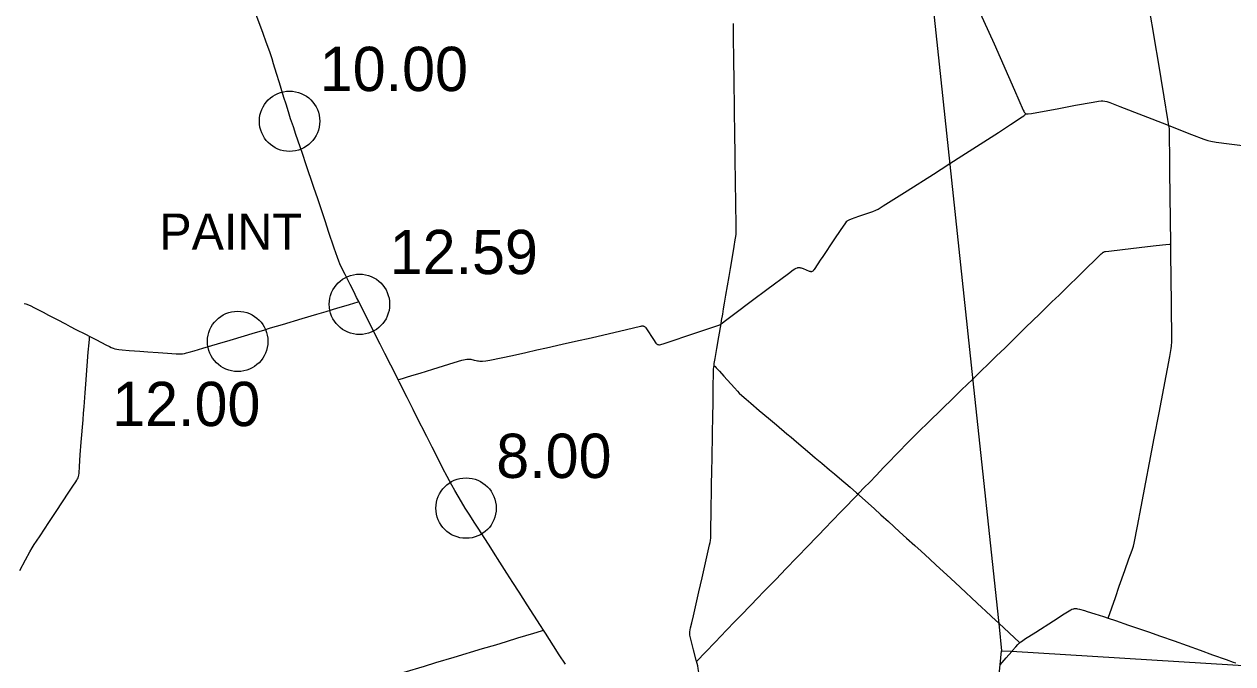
# Model space of a CAD drawing. Extents: x 1597222 to 1925846, y 496284 to 911751.
# Drawn here: x 1697422 to 1727439, y 592663 to 608558 of the extents above; entities that cross this region are included whole.
import ezdxf

# ---------------------------------------------------------------- set-up
doc = ezdxf.new("R2010")
doc.units = 0
for name, color, linetype in [('Default', 7, 'Continuous'), ('GM_X_County_Road', 7, 'Continuous'), ('GM_X_State_Route', 7, 'Continuous'), ('GM_X_Township', 7, 'Continuous'), ('GM_X_Township_Road', 7, 'Continuous'), ('GM_X_Township_Text', 7, 'Continuous')]:
    doc.layers.add(name, color=color, linetype=linetype)

msp = doc.modelspace()

# ---------------------------------------------------------------- linework, layer by layer
at = {"layer": 'Default'}
for centre in [(1704013, 606146), (1704013, 606146), (1705749, 601597), (1705749, 601597), (1702725, 600676), (1702725, 600676), (1708396, 596532), (1708396, 596532)]:
    msp.add_circle(centre, 750, dxfattribs=at)
at = {"layer": 'GM_X_County_Road'}
for points in [[(1719664, 612128), (1719709, 612028), (1720072, 611236), (1720382, 610549), (1720574, 610132), (1720984, 609237), (1721514, 608073), (1722019, 606916), (1722233, 606423), (1722246, 606395), (1722256, 606375), (1722265, 606360), (1722278, 606348), (1722291, 606338), (1722301, 606333)], [(1725853, 606038), (1725852, 606043), (1725828, 606188), (1725733, 606755), (1725581, 607661), (1725508, 608096), (1725457, 608403), (1725348, 609067)], [(1714729, 601108), (1714743, 601191), (1714771, 601353), (1714792, 601482), (1714817, 601628), (1714850, 601822), (1714930, 602291), (1714963, 602485), (1714987, 602631), (1715056, 603035), (1715083, 603197), (1715094, 603278), (1715101, 603343), (1715105, 603408), (1715107, 603490), (1715103, 603736), (1715100, 603916), (1715098, 604047), (1715095, 604244), (1715090, 604506), (1715087, 604720), (1715084, 604851), (1715081, 604998), (1715080, 605195), (1715079, 605326), (1715076, 605474), (1715074, 605687), (1715070, 605851), (1715069, 606031), (1715067, 606195), (1715063, 606425), (1715059, 606688), (1715056, 606934), (1715054, 607147), (1715046, 607672), (1715044, 607852), (1715040, 608049), (1715040, 608246), (1715036, 608574)], [(1722301, 606333), (1722308, 606331), (1722316, 606329), (1722325, 606327), (1722333, 606327), (1722341, 606327), (1722357, 606328), (1722439, 606341), (1723117, 606465), (1723536, 606543), (1723972, 606624), (1724101, 606645), (1724166, 606651), (1724214, 606650), (1724260, 606646), (1724310, 606633), (1724388, 606608), (1724632, 606513), (1725794, 606061), (1725853, 606038)], [(1720411, 605092), (1720708, 605283), (1720985, 605460), (1721619, 605869), (1721921, 606066), (1722209, 606255), (1722252, 606284), (1722277, 606303), (1722287, 606313), (1722293, 606322), (1722301, 606333)], [(1725853, 606038), (1726415, 605816), (1726722, 605698), (1726816, 605668), (1726896, 605650), (1727026, 605630), (1727351, 605587), (1727936, 605510), (1728701, 605408), (1729335, 605327), (1729562, 605296), (1729626, 605283), (1729673, 605269), (1729718, 605250), (1729760, 605226), (1729829, 605182), (1730604, 604603), (1730959, 604338), (1731603, 603858), (1731787, 603720), (1731905, 603631), (1732099, 603483), (1732167, 603429)], [(1725897, 603097), (1725877, 604895), (1725872, 605453), (1725867, 605469), (1725871, 605486), (1725870, 605535), (1725864, 605945), (1725863, 605969), (1725859, 606002), (1725853, 606038)], [(1714729, 601108), (1714738, 601114), (1714757, 601130), (1714803, 601167), (1715038, 601342), (1715511, 601696), (1715866, 601962), (1716404, 602366), (1716522, 602454), (1716564, 602481), (1716593, 602496), (1716624, 602506), (1716639, 602509), (1716656, 602510), (1716671, 602511), (1716687, 602509), (1716706, 602507), (1716721, 602503), (1716740, 602498), (1716768, 602488), (1716919, 602423), (1716939, 602418), (1716951, 602415), (1716960, 602414), (1716968, 602414), (1716975, 602414), (1716983, 602416), (1716990, 602418), (1716999, 602421), (1717013, 602428), (1717026, 602438), (1717037, 602450), (1717048, 602462), (1717142, 602603), (1717201, 602693), (1717263, 602786), (1717349, 602912), (1717459, 603076), (1717559, 603226), (1717694, 603432), (1717824, 603621), (1717856, 603659), (1717870, 603672), (1717881, 603680), (1717893, 603688), (1717909, 603697), (1717969, 603721), (1718155, 603786), (1718496, 603906), (1718573, 603935), (1718631, 603964), (1718758, 604041), (1719353, 604419), (1720005, 604831), (1720199, 604955), (1720411, 605092)], [(1720980, 599738), (1721574, 600315), (1721773, 600510), (1722020, 600751), (1722302, 601025), (1722466, 601186), (1722643, 601357), (1722948, 601655), (1723125, 601826), (1723383, 602078), (1723571, 602261), (1723817, 602503), (1724016, 602698), (1724167, 602849), (1724191, 602870), (1724204, 602880), (1724218, 602889), (1724233, 602896), (1724248, 602902), (1724264, 602907), (1724280, 602910), (1724361, 602921), (1724703, 602960), (1725111, 603007), (1725323, 603031), (1725534, 603056), (1725779, 603083), (1725877, 603095), (1725897, 603097)], [(1724345, 593802), (1724523, 594314), (1724620, 594593), (1724757, 594979), (1724860, 595274), (1724938, 595489), (1724969, 595583), (1724989, 595663), (1725070, 596082), (1725160, 596566), (1725487, 598274), (1725606, 598902), (1725723, 599515), (1725875, 600304), (1725909, 600498), (1725917, 600558), (1725920, 600596), (1725922, 600629), (1725923, 600679), (1725913, 601614), (1725900, 602861), (1725897, 603097)], [(1706709, 599724), (1706727, 599729), (1706814, 599756), (1706914, 599787), (1707052, 599829), (1707256, 599890), (1707570, 599987), (1708104, 600148), (1708292, 600207), (1708371, 600228), (1708419, 600236), (1708428, 600237), (1708440, 600238), (1708452, 600238), (1708468, 600237), (1708492, 600235), (1708517, 600231), (1708601, 600212), (1708646, 600200), (1708677, 600194), (1708703, 600189), (1708742, 600185), (1708808, 600184), (1708889, 600191), (1708986, 600207), (1709548, 600329), (1709884, 600403), (1710156, 600463), (1710396, 600519), (1710780, 600605), (1711116, 600682), (1711501, 600768), (1712380, 600971), (1712731, 601055), (1712747, 601058), (1712765, 601060), (1712780, 601061), (1712796, 601059), (1712805, 601057), (1712812, 601054), (1712826, 601046), (1712839, 601037), (1712849, 601026), (1712861, 601013), (1713067, 600696), (1713094, 600655), (1713110, 600634), (1713126, 600617), (1713139, 600608), (1713154, 600601), (1713169, 600596), (1713185, 600593), (1713202, 600593), (1713234, 600598), (1713313, 600622), (1714105, 600891), (1714650, 601074), (1714697, 601088), (1714706, 601093), (1714712, 601096), (1714721, 601102), (1714729, 601108)], [(1714554, 600072), (1714561, 600124), (1714582, 600254), (1714624, 600496), (1714675, 600787), (1714729, 601108)], [(1714122, 592728), (1714115, 592755), (1714049, 593009), (1713976, 593278), (1713960, 593342), (1713954, 593375), (1713951, 593408), (1713951, 593425), (1713953, 593458), (1713959, 593507), (1713969, 593555), (1714000, 593683), (1714042, 593859), (1714124, 594227), (1714177, 594450), (1714257, 594802), (1714308, 595026), (1714392, 595394), (1714445, 595617), (1714457, 595682), (1714465, 595730), (1714472, 595795), (1714475, 595860), (1714479, 596057), (1714483, 596385), (1714486, 596549), (1714487, 596696), (1714488, 596795), (1714493, 597041), (1714502, 597517), (1714505, 597713), (1714509, 597959), (1714513, 598189), (1714515, 598353), (1714517, 598484), (1714521, 598714), (1714530, 599239), (1714537, 599583), (1714541, 599862), (1714545, 599977), (1714550, 600042), (1714554, 600072)], [(1718131, 596883), (1718147, 596900), (1718285, 597041), (1718422, 597181), (1718581, 597347), (1718775, 597548), (1719208, 597996), (1719288, 598079), (1719448, 598243), (1719645, 598440), (1719880, 598670), (1719985, 598773), (1720103, 598887), (1720245, 599024), (1720458, 599228), (1720703, 599469), (1720980, 599738)], [(1714122, 592728), (1714125, 592731), (1714345, 592956), (1714585, 593203), (1714868, 593500), (1715073, 593712), (1715244, 593889), (1715654, 594314), (1715779, 594444), (1716087, 594762), (1716350, 595033), (1716599, 595294), (1716907, 595612), (1717078, 595789), (1717180, 595896), (1717282, 596002), (1717521, 596250), (1717680, 596416), (1717852, 596593), (1717999, 596747), (1718131, 596883)], [(1722148, 593186), (1722174, 593209), (1722213, 593238), (1722267, 593275), (1722543, 593453), (1722985, 593735), (1723247, 593903), (1723372, 593983), (1723414, 594006), (1723444, 594020), (1723474, 594030), (1723490, 594034), (1723505, 594036), (1723521, 594038), (1723537, 594038), (1723553, 594038), (1723585, 594033), (1723633, 594022), (1723758, 593985), (1723821, 593966), (1724009, 593907), (1724228, 593840), (1724345, 593802)], [(1724345, 593802), (1724527, 593740), (1724852, 593628), (1725347, 593455), (1725641, 593354), (1725980, 593232), (1726628, 592999), (1726937, 592890), (1727275, 592768), (1727446, 592708), (1727515, 592688)], [(1704440, 591727), (1704453, 591735), (1704484, 591750), (1704531, 591767), (1704609, 591792), (1704939, 591889), (1705191, 591965), (1705553, 592072), (1705820, 592151), (1706024, 592211), (1706213, 592267), (1706858, 592459), (1707361, 592609), (1707644, 592693), (1708100, 592829), (1708807, 593041), (1709137, 593139), (1709404, 593220), (1709686, 593306), (1710079, 593425), (1710273, 593483), (1710321, 593498)], [(1721949, 592973), (1721959, 592985), (1722046, 593083), (1722102, 593143), (1722137, 593177), (1722148, 593186)], [(1721661, 592638), (1721810, 592811), (1721949, 592973)], [(1714223, 589412), (1714224, 589467), (1714225, 589697), (1714224, 590320), (1714221, 590529), (1714217, 590679), (1714215, 590795), (1714210, 591008), (1714206, 591189), (1714202, 591369), (1714195, 591631), (1714191, 591763), (1714187, 591992), (1714179, 592386), (1714176, 592451), (1714172, 592500), (1714164, 592548), (1714151, 592612), (1714122, 592728)]]:
    msp.add_lwpolyline(points, dxfattribs=at)
at = {"layer": 'GM_X_State_Route'}
for points in [[(1705732, 601663), (1705679, 601767), (1705606, 601914), (1705518, 602090), (1705391, 602338), (1705304, 602515), (1705262, 602604), (1705238, 602665), (1705204, 602757), (1705124, 602990), (1704984, 603410), (1704905, 603643), (1704852, 603798), (1704779, 604016), (1704711, 604218), (1704619, 604499), (1704549, 604700), (1704487, 604887), (1704419, 605089), (1704341, 605322), (1704218, 605679), (1704171, 605819), (1704108, 606005), (1704040, 606208), (1703986, 606380), (1703927, 606567), (1703873, 606740), (1703806, 606959), (1703763, 607101), (1703689, 607335), (1703617, 607571), (1703578, 607696), (1703520, 607867), (1703433, 608115), (1703354, 608330), (1703297, 608484), (1703183, 608792)], [(1697420, 601620), (1697467, 601605), (1697529, 601582), (1697589, 601557), (1697663, 601521), (1697765, 601467), (1697895, 601398), (1698026, 601330), (1698244, 601217), (1698448, 601110), (1698564, 601049), (1698709, 600974), (1698943, 600855), (1699049, 600800), (1699220, 600711), (1699452, 600589), (1699540, 600545), (1699584, 600525), (1699630, 600507), (1699676, 600492), (1699724, 600481), (1699772, 600474), (1699853, 600465), (1700033, 600450), (1700294, 600432), (1700491, 600418), (1700752, 600400), (1700981, 600383), (1701194, 600369), (1701259, 600366), (1701308, 600367), (1701357, 600370), (1701405, 600377), (1701453, 600388), (1701516, 600406), (1701641, 600445), (1701861, 600510), (1702223, 600617), (1702537, 600710), (1703166, 600896), (1703371, 600955), (1703543, 601009), (1703841, 601099), (1704328, 601245), (1704690, 601353), (1704926, 601422), (1705209, 601506), (1705476, 601585), (1705633, 601633), (1705695, 601652), (1705732, 601663)], [(1710864, 592653), (1710712, 592887), (1710572, 593109), (1710367, 593426), (1710321, 593498), (1710243, 593619), (1709916, 594131), (1709712, 594448), (1709562, 594683), (1709410, 594917), (1709233, 595193), (1709074, 595442), (1708968, 595608), (1708844, 595801), (1708712, 596008), (1708615, 596161), (1708472, 596381), (1708376, 596534), (1708282, 596688), (1708115, 596970), (1708043, 597099), (1707927, 597316), (1707821, 597519), (1707702, 597754), (1707554, 598046), (1707421, 598310), (1707169, 598808), (1707082, 598984), (1706935, 599278), (1706735, 599672), (1706709, 599724), (1706624, 599892), (1706530, 600084), (1706381, 600376), (1706263, 600610), (1706101, 600933), (1705990, 601152), (1705827, 601474), (1705732, 601663)]]:
    msp.add_lwpolyline(points, dxfattribs=at)
at = {"layer": 'GM_X_Township'}
for points in [[(1718727, 620944), (1719007, 618308), (1719624, 612493), (1719675, 612012), (1720412, 605075), (1720984, 599696), (1721634, 593580), (1721696, 592990)], [(1720855, 576610), (1720323, 577460), (1720153, 577816), (1720749, 583791), (1720924, 585495), (1721014, 586371), (1721660, 592640), (1721696, 592990), (1721944, 592975), (1727437, 592635), (1742617, 591697)]]:
    msp.add_lwpolyline(points, dxfattribs=at)
at = {"layer": 'GM_X_Township_Road'}
for points in [[(1697313, 594986), (1697452, 595246), (1697563, 595447), (1697621, 595547), (1697673, 595630), (1697727, 595712), (1697819, 595848), (1697927, 596012), (1698034, 596177), (1698199, 596423), (1698388, 596711), (1698517, 596901), (1698633, 597079), (1698707, 597188), (1698733, 597229), (1698749, 597258), (1698761, 597289), (1698771, 597320), (1698778, 597352), (1698784, 597401), (1698796, 597564), (1698816, 597859), (1698840, 598170), (1698884, 598726), (1698896, 598889), (1698908, 599053), (1698934, 599396), (1698951, 599609), (1698988, 600067), (1699014, 600410), (1699032, 600639), (1699041, 600731), (1699045, 600770), (1699049, 600800)], [(1714554, 600072), (1714567, 600064), (1714576, 600058), (1714583, 600051), (1714611, 600022), (1714687, 599936), (1714797, 599815), (1715059, 599521), (1715136, 599436), (1715183, 599389), (1715243, 599334), (1715354, 599237), (1715467, 599142), (1715679, 598961), (1715904, 598770), (1716104, 598600), (1716366, 598376), (1716467, 598293), (1716605, 598176), (1716767, 598038), (1716930, 597901), (1717068, 597784), (1717230, 597646), (1717419, 597488), (1717543, 597381), (1717668, 597275), (1717932, 597053), (1718095, 596915), (1718131, 596883)], [(1718131, 596883), (1718168, 596849), (1718533, 596520), (1718701, 596364), (1718884, 596199), (1719164, 595946), (1719333, 595790), (1719540, 595604), (1719698, 595461), (1719904, 595273), (1720074, 595119), (1720339, 594874), (1720543, 594684), (1720807, 594438), (1720951, 594303), (1721083, 594181), (1721215, 594058), (1721287, 593991), (1721454, 593833), (1721628, 593670)], [(1721628, 593670), (1722143, 593191), (1722148, 593186)]]:
    msp.add_lwpolyline(points, dxfattribs=at)

# ---------------------------------------------------------------- texts
at = {"layer": 'Default'}
for s, p in [('10.00', (1704763, 606896)), ('10.00', (1704763, 606896)), ('12.59', (1706499, 602347)), ('12.59', (1706499, 602347)), ('12.00', (1699608, 598571)), ('12.00', (1699608, 598571)), ('8.00', (1709146, 597282)), ('8.00', (1709146, 597282))]:
    msp.add_text(s, height=1100, dxfattribs=at).set_placement(p)
at = {"layer": 'GM_X_Township_Text'}
msp.add_text('PAINT', height=900, rotation=0, dxfattribs=at).set_placement((1700778, 602953))

doc.saveas('drawing.dxf')
